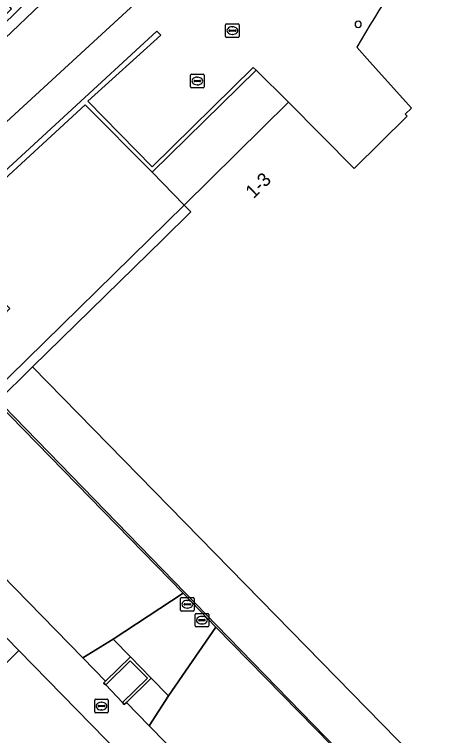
# Model space of a CAD drawing. Extents: x 161402 to 161933, y 381647 to 382315.
# Drawn here: x 161720.1 to 161751.9, y 382163.3 to 382216.4 of the extents above; entities that cross this region are included whole.
import ezdxf

# ---------------------------------------------------------------- set-up
doc = ezdxf.new("R2010")
doc.units = 0
for name, color, linetype in [('IMGEO_Berm_groen', 7, 'Continuous'), ('IMGEO_Groenvoorziening', 7, 'Continuous'), ('IMGEO_Hek', 7, 'Continuous'), ('IMGEO_Kolk', 7, 'Continuous'), ('IMGEO_Muur', 7, 'Continuous'), ('IMGEO_Pand', 7, 'Continuous'), ('IMGEO_Pand_nummerreeks', 7, 'Continuous'), ('IMGEO_Pand_overbouw', 7, 'Continuous'), ('IMGEO_Rijbaan_lokaal_open', 7, 'Continuous'), ('IMGEO_Rioolput', 7, 'Continuous'), ('IMGEO_Voetpad_gesloten', 7, 'Continuous'), ('IMGEO_Voetpad_op_trap', 7, 'Continuous'), ('IMGEO_Voetpad_open', 7, 'Continuous')]:
    doc.layers.add(name, color=color, linetype=linetype)

msp = doc.modelspace()

# ---------------------------------------------------------------- linework, layer by layer
at = {"layer": 'IMGEO_Berm_groen'}
msp.add_lwpolyline([(161711.914, 382207.765), (161713.169, 382208.748), (161728.253, 382223.117), (161748.845, 382243.038), (161748.046, 382243.815), (161715.85, 382212.342), (161715.57, 382212.632), (161719.892, 382216.863), (161719.584, 382217.248), (161747.1, 382244.24)], dxfattribs=at)
at = {"layer": 'IMGEO_Groenvoorziening'}
for points in [[(161718.791, 382187.892), (161718.303, 382188.391), (161712.113, 382182.395), (161725.159, 382169.045), (161727.393, 382170.437), (161732.558, 382173.814)], [(161734.96, 382171.316), (161731.457, 382166.262), (161730.041, 382164.042), (161750.723, 382142.947), (161756.887, 382148.953)]]:
    msp.add_lwpolyline(points, close=True, dxfattribs=at)
for points in [[(161711.9, 382174.979), (161713.7, 382173.074), (161718.648, 382167.837), (161720.442, 382169.591), (161715.996, 382174.137)], [(161720.442, 382169.591), (161718.648, 382167.837), (161705.768, 382155.422), (161707.185, 382150.486), (161710.232, 382147.786), (161723.154, 382151.883), (161730.025, 382147.128), (161730.669, 382146.181), (161734.412, 382149.757)], [(161734.284, 382155.436), (161720.442, 382169.591)]]:
    msp.add_lwpolyline(points, dxfattribs=at)
at = {"layer": 'IMGEO_Hek'}
msp.add_lwpolyline([(161726.851, 382167.068), (161728.078, 382165.762)], dxfattribs=at)
at = {"layer": 'IMGEO_Kolk'}
for p, q in [((161726.025, 382165.074), (161726.025, 382165.926)), ((161726.1, 382166), (161726.952, 382166)), ((161727.026, 382165.926), (161727.026, 382165.074)), ((161726.284, 382165.494), (161726.284, 382165.506)), ((161726.722, 382165.457), (161726.324, 382165.457)), ((161726.327, 382165.543), (161726.725, 382165.543)), ((161726.513, 382165.78), (161726.538, 382165.78)), ((161726.768, 382165.506), (161726.768, 382165.494)), ((161726.952, 382165), (161726.1, 382165)), ((161726.536, 382165.22), (161726.511, 382165.22))]:
    msp.add_line(p, q, dxfattribs=at)
for points in [[(161726.025, 382165.074), (161726.025, 382165.926)], [(161726.1, 382166), (161726.952, 382166)], [(161727.026, 382165.926), (161727.026, 382165.074)], [(161726.952, 382165), (161726.1, 382165)]]:
    msp.add_lwpolyline(points, dxfattribs=at)
for centre, radius, start, end in [((161726.102, 382165.924), 0.0765, 91.552, 178.448), ((161726.102, 382165.924), 0.0765, 91.552, 178.448), ((161726.95, 382165.924), 0.0765, 1.552, 88.448), ((161726.95, 382165.924), 0.0765, 1.552, 88.448), ((161726.324, 382165.503), 0.0403, 85.8775, 175.7526), ((161726.321, 382165.493), 0.0366, 178.938, 274.7102), ((161726.725, 382165.5), 0.043, 264.8664, 352.4533), ((161726.729, 382165.505), 0.0386, 1.7309, 96.639), ((161726.102, 382165.076), 0.0765, 181.552, 268.448), ((161726.102, 382165.076), 0.0765, 181.552, 268.448), ((161726.95, 382165.076), 0.0765, 271.552, 358.448), ((161726.95, 382165.076), 0.0765, 271.552, 358.448)]:
    msp.add_arc(centre, radius, start, end, dxfattribs=at)
for centre, major_axis, ratio, start_param, end_param in [((161726.512, 382165.5), (-0.387, 0.002), 0.722429, 4.712389, 7.853982), ((161726.537, 382165.5), (-0.39, 0.002), 0.717154, 1.570796, 4.712389)]:
    msp.add_ellipse(centre, major_axis=major_axis, ratio=ratio, start_param=start_param, end_param=end_param, dxfattribs=at)
at = {"layer": 'IMGEO_Muur'}
for points in [[(161710.58, 382196.249), (161714.96, 382200.272), (161725.317, 382209.785), (161730.255, 382204.824), (161737.927, 382212.338), (161737.712, 382212.535), (161730.265, 382205.223), (161725.521, 382210.052), (161730.896, 382214.926), (161730.601, 382215.217), (161703.725, 382190.486), (161703.837, 382190.381), (161704.004, 382190.216), (161704.26, 382190.444)], [(161728.661, 382169.134), (161726.833, 382167.332), (161726.677, 382167.178), (161726.851, 382167.068), (161728.644, 382168.842), (161729.907, 382167.555), (161728.078, 382165.762), (161728.206, 382165.605), (161728.36, 382165.756), (161730.192, 382167.561)]]:
    msp.add_lwpolyline(points, close=True, dxfattribs=at)
at = {"layer": 'IMGEO_Pand'}
msp.add_lwpolyline([(161745.352, 382214.033), (161746.316, 382212.958), (161749.374, 382209.55), (161748.921, 382209.103), (161749.061, 382208.961), (161745.139, 382205.091), (161740.314, 382209.981), (161732.627, 382202.397), (161733.12, 382201.899), (161731.074, 382199.9), (161721.45, 382190.492), (161759.531, 382151.588)], dxfattribs=at)
for centre, radius, start, end in [((161816.968, 382172.845), 82.616, 143.12172, 150.09585), ((161745.445, 382215.72), 0.23, 90, 270), ((161745.445, 382215.72), 0.23, 270, 90)]:
    msp.add_arc(centre, radius, start, end, dxfattribs=at)
at = {"layer": 'IMGEO_Pand_overbouw'}
msp.add_lwpolyline([(161761.891, 382149.186), (161762.139, 382149.42), (161762.295, 382149.283), (161763.101, 382150.057), (161760.483, 382152.716), (161759.531, 382151.588), (161721.45, 382190.492), (161731.074, 382199.9), (161733.12, 382201.899), (161732.627, 382202.397), (161718.426, 382188.506), (161732.696, 382173.838), (161734.999, 382171.47), (161749.249, 382156.824), (161751.751, 382159.273), (161759.445, 382151.424), (161759.582, 382151.549)], close=True, dxfattribs=at)
at = {"layer": 'IMGEO_Rijbaan_lokaal_open'}
for points in [[(161766.659, 382260.549), (161751.001, 382245.149), (161748.845, 382243.038), (161728.253, 382223.117), (161713.169, 382208.748), (161711.914, 382207.765)], [(161710.972, 382200.713), (161733.859, 382221.725), (161739.772, 382227.133), (161755.602, 382242.666)]]:
    msp.add_lwpolyline(points, dxfattribs=at)
at = {"layer": 'IMGEO_Rioolput'}
for p, q in [((161735.751, 382215.756), (161736.603, 382215.756)), ((161735.676, 382214.83), (161735.676, 382215.682)), ((161735.935, 382215.25), (161735.935, 382215.262)), ((161736.373, 382215.213), (161735.975, 382215.213)), ((161735.978, 382215.299), (161736.376, 382215.299)), ((161736.164, 382215.536), (161736.189, 382215.536)), ((161736.419, 382215.262), (161736.419, 382215.25)), ((161736.677, 382215.682), (161736.677, 382214.83)), ((161736.603, 382214.756), (161735.751, 382214.756)), ((161736.187, 382214.976), (161736.162, 382214.976)), ((161733.163, 382212.045), (161734.015, 382212.045)), ((161733.088, 382211.119), (161733.088, 382211.971)), ((161733.347, 382211.539), (161733.347, 382211.551)), ((161733.785, 382211.502), (161733.387, 382211.502)), ((161733.39, 382211.588), (161733.788, 382211.588)), ((161733.576, 382211.825), (161733.601, 382211.825)), ((161733.831, 382211.551), (161733.831, 382211.539)), ((161734.089, 382211.971), (161734.089, 382211.119)), ((161734.015, 382211.045), (161733.163, 382211.045)), ((161733.599, 382211.265), (161733.574, 382211.265)), ((161732.355, 382172.571), (161732.355, 382173.423)), ((161732.43, 382173.497), (161733.282, 382173.497)), ((161732.843, 382173.277), (161732.868, 382173.277)), ((161733.356, 382173.423), (161733.356, 382172.571)), ((161732.614, 382172.991), (161732.614, 382173.003)), ((161733.052, 382172.954), (161732.654, 382172.954)), ((161732.657, 382173.04), (161733.055, 382173.04)), ((161732.866, 382172.717), (161732.841, 382172.717)), ((161733.098, 382173.003), (161733.098, 382172.991)), ((161733.282, 382172.497), (161732.43, 382172.497)), ((161733.429, 382171.402), (161733.429, 382172.254)), ((161733.504, 382172.328), (161734.356, 382172.328)), ((161734.43, 382172.254), (161734.43, 382171.402)), ((161733.688, 382171.822), (161733.688, 382171.834)), ((161734.126, 382171.785), (161733.728, 382171.785)), ((161733.731, 382171.871), (161734.129, 382171.871)), ((161733.917, 382172.108), (161733.942, 382172.108)), ((161734.172, 382171.834), (161734.172, 382171.822)), ((161734.356, 382171.328), (161733.504, 382171.328)), ((161733.94, 382171.548), (161733.915, 382171.548))]:
    msp.add_line(p, q, dxfattribs=at)
for points in [[(161735.751, 382215.756), (161736.603, 382215.756)], [(161735.676, 382214.83), (161735.676, 382215.682)], [(161736.677, 382215.682), (161736.677, 382214.83)], [(161736.603, 382214.756), (161735.751, 382214.756)], [(161733.163, 382212.045), (161734.015, 382212.045)], [(161733.088, 382211.119), (161733.088, 382211.971)], [(161734.089, 382211.971), (161734.089, 382211.119)], [(161734.015, 382211.045), (161733.163, 382211.045)], [(161732.355, 382172.571), (161732.355, 382173.423)], [(161732.43, 382173.497), (161733.282, 382173.497)], [(161733.356, 382173.423), (161733.356, 382172.571)], [(161733.282, 382172.497), (161732.43, 382172.497)], [(161733.429, 382171.402), (161733.429, 382172.254)], [(161733.504, 382172.328), (161734.356, 382172.328)], [(161734.43, 382172.254), (161734.43, 382171.402)], [(161734.356, 382171.328), (161733.504, 382171.328)]]:
    msp.add_lwpolyline(points, dxfattribs=at)
for centre, radius, start, end in [((161735.753, 382215.68), 0.0765, 91.552, 178.448), ((161735.753, 382215.68), 0.0765, 91.552, 178.448), ((161736.601, 382215.68), 0.0765, 1.552, 88.448), ((161736.601, 382215.68), 0.0765, 1.552, 88.448), ((161735.975, 382215.259), 0.0403, 85.8775, 175.7526), ((161735.972, 382215.249), 0.0366, 178.938, 274.7102), ((161736.376, 382215.256), 0.043, 264.8664, 352.4533), ((161736.38, 382215.261), 0.0386, 1.7309, 96.639), ((161735.753, 382214.832), 0.0765, 181.552, 268.448), ((161735.753, 382214.832), 0.0765, 181.552, 268.448), ((161736.601, 382214.832), 0.0765, 271.552, 358.448), ((161736.601, 382214.832), 0.0765, 271.552, 358.448), ((161733.165, 382211.969), 0.0765, 91.552, 178.448), ((161733.165, 382211.969), 0.0765, 91.552, 178.448), ((161734.013, 382211.969), 0.0765, 1.552, 88.448), ((161734.013, 382211.969), 0.0765, 1.552, 88.448), ((161733.387, 382211.548), 0.0403, 85.8775, 175.7526), ((161733.384, 382211.538), 0.0366, 178.938, 274.7102), ((161733.788, 382211.545), 0.043, 264.8664, 352.4533), ((161733.792, 382211.55), 0.0386, 1.7309, 96.639), ((161733.165, 382211.121), 0.0765, 181.552, 268.448), ((161733.165, 382211.121), 0.0765, 181.552, 268.448), ((161734.013, 382211.121), 0.0765, 271.552, 358.448), ((161734.013, 382211.121), 0.0765, 271.552, 358.448), ((161732.432, 382173.421), 0.0765, 91.552, 178.448), ((161732.432, 382173.421), 0.0765, 91.552, 178.448), ((161733.28, 382173.421), 0.0765, 1.552, 88.448), ((161733.28, 382173.421), 0.0765, 1.552, 88.448), ((161732.654, 382173), 0.0403, 85.8775, 175.7526), ((161732.651, 382172.99), 0.0366, 178.938, 274.7102), ((161733.055, 382172.997), 0.043, 264.8664, 352.4533), ((161733.059, 382173.002), 0.0386, 1.7309, 96.639), ((161732.432, 382172.573), 0.0765, 181.552, 268.448), ((161732.432, 382172.573), 0.0765, 181.552, 268.448), ((161733.28, 382172.573), 0.0765, 271.552, 358.448), ((161733.28, 382172.573), 0.0765, 271.552, 358.448), ((161733.506, 382172.252), 0.0765, 91.552, 178.448), ((161733.506, 382172.252), 0.0765, 91.552, 178.448), ((161734.354, 382172.252), 0.0765, 1.552, 88.448), ((161734.354, 382172.252), 0.0765, 1.552, 88.448), ((161733.728, 382171.831), 0.0403, 85.8775, 175.7526), ((161733.725, 382171.821), 0.0366, 178.938, 274.7102), ((161734.129, 382171.828), 0.043, 264.8664, 352.4533), ((161734.133, 382171.833), 0.0386, 1.7309, 96.639), ((161733.506, 382171.404), 0.0765, 181.552, 268.448), ((161733.506, 382171.404), 0.0765, 181.552, 268.448), ((161734.354, 382171.404), 0.0765, 271.552, 358.448), ((161734.354, 382171.404), 0.0765, 271.552, 358.448)]:
    msp.add_arc(centre, radius, start, end, dxfattribs=at)
for centre, major_axis, ratio, start_param, end_param in [((161736.163, 382215.256), (-0.387, 0.002), 0.722429, 4.712389, 7.853982), ((161736.188, 382215.256), (-0.39, 0.002), 0.717154, 1.570796, 4.712389), ((161733.575, 382211.545), (-0.387, 0.002), 0.722429, 4.712389, 7.853982), ((161733.6, 382211.545), (-0.39, 0.002), 0.717154, 1.570796, 4.712389), ((161732.842, 382172.997), (-0.387, 0.002), 0.722429, 4.712389, 7.853982), ((161732.867, 382172.997), (-0.39, 0.002), 0.717154, 1.570796, 4.712389), ((161733.916, 382171.828), (-0.387, 0.002), 0.722429, 4.712389, 7.853982), ((161733.941, 382171.828), (-0.39, 0.002), 0.717154, 1.570796, 4.712389)]:
    msp.add_ellipse(centre, major_axis=major_axis, ratio=ratio, start_param=start_param, end_param=end_param, dxfattribs=at)
at = {"layer": 'IMGEO_Voetpad_gesloten'}
for points in [[(161734.96, 382171.316), (161732.558, 382173.814), (161727.393, 382170.437), (161728.661, 382169.134), (161730.192, 382167.561), (161731.457, 382166.262)], [(161726.851, 382167.068), (161728.078, 382165.762), (161729.907, 382167.555), (161728.644, 382168.842)]]:
    msp.add_lwpolyline(points, close=True, dxfattribs=at)
at = {"layer": 'IMGEO_Voetpad_op_trap'}
for points in [[(161740.314, 382209.981), (161737.927, 382212.338), (161730.255, 382204.824), (161732.627, 382202.397)], [(161728.661, 382169.134), (161727.393, 382170.437), (161725.159, 382169.045), (161726.833, 382167.332)], [(161731.457, 382166.262), (161730.192, 382167.561), (161728.36, 382165.756), (161730.041, 382164.042)]]:
    msp.add_lwpolyline(points, close=True, dxfattribs=at)
at = {"layer": 'IMGEO_Voetpad_open'}
for points in [[(161832.261, 382288.126), (161785.98, 382272.346), (161785.755, 382272.254), (161777.222, 382263.881), (161755.602, 382242.666), (161739.772, 382227.133), (161733.859, 382221.725), (161710.972, 382200.713)], [(161702.827, 382189.164), (161704.004, 382190.216), (161703.837, 382190.381), (161703.725, 382190.486), (161730.601, 382215.217)], [(161730.601, 382215.217), (161730.896, 382214.926), (161725.521, 382210.052), (161730.265, 382205.223), (161737.712, 382212.535), (161737.927, 382212.338), (161740.314, 382209.981), (161745.139, 382205.091), (161749.061, 382208.961), (161748.921, 382209.103), (161749.374, 382209.55), (161746.316, 382212.958), (161745.352, 382214.033)], [(161730.041, 382164.042), (161728.36, 382165.756), (161728.206, 382165.605), (161728.078, 382165.762), (161726.851, 382167.068), (161726.677, 382167.178), (161726.833, 382167.332), (161725.159, 382169.045), (161712.113, 382182.395), (161709.733, 382184.826), (161704.26, 382190.444), (161704.004, 382190.216), (161702.827, 382189.164)], [(161703.416, 382187.001), (161705.138, 382185.225), (161707.862, 382182.415), (161709.983, 382180.263), (161710.463, 382179.785), (161710.82, 382179.437), (161713.556, 382176.643), (161715.56, 382174.57), (161715.996, 382174.137), (161720.442, 382169.591), (161734.284, 382155.436)], [(161742.138, 382147.408), (161750.169, 382139.212), (161750.502, 382138.879), (161751.271, 382138.167), (161751.665, 382137.841), (161752.08, 382137.51), (161752.907, 382136.967), (161755.019, 382135.782), (161757.795, 382134.141), (161760.623, 382132.511), (161760.865, 382132.357), (161761.508, 382132.036), (161765.481, 382129.756), (161779.35, 382121.795), (161781.022, 382124.329), (161753.587, 382140.004), (161753.075, 382140.488), (161750.723, 382142.947), (161730.041, 382164.042)]]:
    msp.add_lwpolyline(points, dxfattribs=at)
for points in [[(161731.074, 382199.9), (161733.12, 382201.899), (161732.627, 382202.397), (161730.255, 382204.824), (161725.317, 382209.785), (161714.96, 382200.272), (161716.277, 382198.954), (161716.629, 382199.284), (161718.739, 382197.199), (161718.363, 382196.845), (161718.73, 382196.486), (161718.37, 382196.141), (161719.778, 382194.789), (161717.998, 382192.949), (161716.96, 382194.032), (161714.804, 382191.965), (161715.942, 382190.81), (161718.303, 382188.391), (161718.791, 382187.892), (161721.45, 382190.492)], [(161762.198, 382148.594), (161761.744, 382149.047), (161761.891, 382149.186), (161762.139, 382149.42), (161762.295, 382149.283), (161763.101, 382150.057), (161760.483, 382152.716), (161759.531, 382151.588), (161721.45, 382190.492), (161718.791, 382187.892), (161732.558, 382173.814), (161734.96, 382171.316), (161756.887, 382148.953), (161759.272, 382146.53), (161759.72, 382146.044), (161759.814, 382145.96), (161781.022, 382124.329), (161784.015, 382126.305)]]:
    msp.add_lwpolyline(points, close=True, dxfattribs=at)
for centre, radius, start, end in [((161816.968, 382172.845), 82.616, 143.12172, 150.09585), ((161745.445, 382215.72), 0.23, 90, 270), ((161745.445, 382215.72), 0.23, 270, 90)]:
    msp.add_arc(centre, radius, start, end, dxfattribs=at)

# ---------------------------------------------------------------- texts
at = {"layer": 'IMGEO_Pand_nummerreeks'}
msp.add_text('1-3', height=1, rotation=44.616, dxfattribs=at).set_placement((161737.735, 382202.829))

doc.saveas('drawing.dxf')
